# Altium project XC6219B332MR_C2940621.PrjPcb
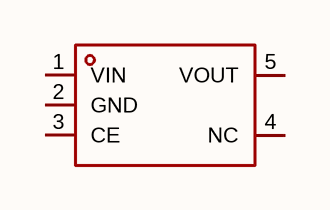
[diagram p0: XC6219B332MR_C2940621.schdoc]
1 sheet, 1 parts. Net scope: global (net labels, ports and power ports of the same name join across sheets).

## Sheet XC6219B332MR_C2940621.schdoc
size 127 x 101 mm

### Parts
U?  xc6219b332mr  [SOT-23-5_L2.9-W1.6-P0.95-LS2.8-BR]  (value not drawn)

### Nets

Not connected (* = marked no-connect by the designer): U? 1(VIN) 2(GND) 3(CE) 4(NC) 5(VOUT)

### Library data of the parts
U? = xc6219b332mr: 输出极性:正极;工作电压:6V;输出电压:3.3V;输出电流:300mA;电源纹波抑制比(PSRR):70dB@(1kHz);输出类型:固定;; Manufacturer: TECH PUBLIC(台舟); Symbol: XC6219B332MR_C2940621; AddInBom: yes; ModelId: 7ba65df16e7b4570af156e925f9c37fe; ModelTransform: 114.173,114.173,0,90,0,0,0,0,0; Output Configuration: 正极; Voltage - Supply: 6V; Output Voltage: 3.3V; Output Current: 300mA; Voltage Dropout: 90mV@(100mA)；230mV@(200mA); standby current: 70uA; Noise: 50uVrms; Output Type: 固定; Number of Outputs: 1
